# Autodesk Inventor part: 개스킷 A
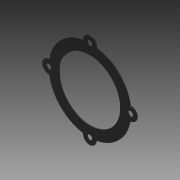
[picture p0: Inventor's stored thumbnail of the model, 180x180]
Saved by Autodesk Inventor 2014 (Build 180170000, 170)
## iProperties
Created: 2020-03
Part Number: 개스킷 A
Material: 고무
Document SubType Name: Modeling
Designer: mduedu
Density: 0.93 g/cm^3
Mass: 2.68337 g
Surface Area: 63.575 cm^2
Volume: 2.88534 cm^3
Appearance: 고무 - 검은색 - 버전 1.1
Author: mduedu
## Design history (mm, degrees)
sketch "스케치1" dims "d1" = 88
  geometry: C1 r 33 at (0, 0); C2 r 7 at (0, 44); C3 r 7 at (-38.105, -22); C4 r 7 at (38.105, -22); 2 further points
  constraints: 4 centre point, 2 coincident, 2 vertical alignment, 9 other
  dimensions: "d0" = 66 diameter of C1; "d2" = 14 diameter of C2; "d5" = 360 deg dimension on point (0, 0) C2.centre (derived)
extrude "돌출1" new body sketch "스케치1" distance "d7" = 1; taper "d8" = 0 deg
extrude "돌출2" join sketch "스케치1" stored distance "d17" = 10; taper "d18" = 0 deg
fillet "모깎기1" dims "d9" = 1
sketch "스케치2"
  geometry: C1 r 33 at (0, 0) reference; A1 r 44 centre (0, 0) between (-7.817, 43.3) and (7.817, 43.3) reference; A2 r 7 centre (0, 44) between (6.996, 44.249) and (-6.996, 44.249) reference; A3 r 1 centre (7.995, 44.284) between (6.996, 44.249) and (7.817, 43.3) reference; A4 r 1 centre (-7.995, 44.284) between (-7.817, 43.3) and (-6.996, 44.249) reference; 4 further points
hole "구멍1" sketch "스케치2" diameter "d10" = 5.5; stored, may be unused: countersink angle "d14" = 90 deg, drill point angle "d16" = 118 deg; dims "d11" = 6, "d12" = 10, "d13" = 5.7, "d15" = 8
node "솔리드1"
pattern_circular "원형 패턴1" dims "d20" = 360 deg
node "투영된 루프1"
